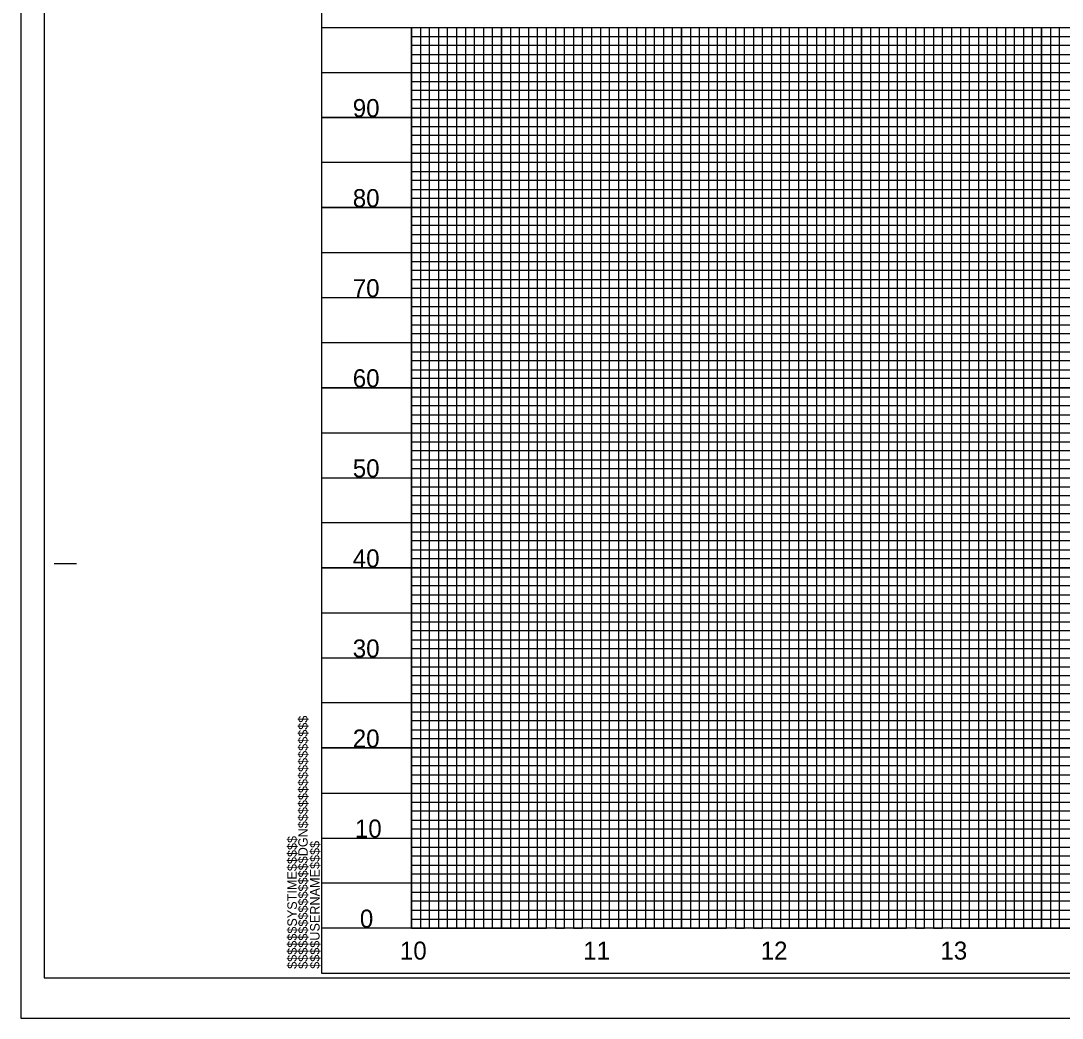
# Model space of a CAD drawing. Extents: x 2186391 to 2188300, y 74582 to 75682.
# Drawn here: x 2186391 to 2186969, y 74582 to 75136 of the extents above; entities that cross this region are included whole.
import ezdxf

# ---------------------------------------------------------------- set-up
doc = ezdxf.new("R2010")
doc.units = 0
for name, color, linetype in [('Old_Level_1', 7, 'Continuous'), ('Old_Level_11', 7, 'Continuous'), ('Old_Level_2', 7, 'Continuous'), ('Old_Level_3', 7, 'Continuous'), ('Scratch_Level_0', 7, 'Continuous'), ('Sheet Border Standard 30in CELL', 7, 'Continuous'), ('Sheet Cutting Line CELL', 7, 'Continuous'), ('Sheet Plot Border Outside CELL', 7, 'Continuous'), ('Sheet Sticker Exception Certification CELL', 7, 'Continuous'), ('Sheet Sticker Incomplete CELL', 7, 'Continuous'), ('Sheet Sticker Preliminary CELL', 7, 'Continuous')]:
    doc.layers.add(name, color=color, linetype=linetype)

msp = doc.modelspace()

# ---------------------------------------------------------------- linework, layer by layer
at = {"layer": 'Old_Level_11'}
for p, q in [((2186557.69, 75132.28), (2188057.58, 75132.28)), ((2186607.69, 75132.28), (2186607.69, 74632.28)), ((2186657.69, 75132.28), (2186657.69, 74632.28)), ((2186707.69, 75132.28), (2186707.69, 74632.28)), ((2186757.69, 75132.28), (2186757.69, 74632.28)), ((2186807.69, 75132.28), (2186807.69, 74632.28)), ((2186857.69, 75132.28), (2186857.69, 74632.28)), ((2186907.69, 75132.28), (2186907.69, 74632.28)), ((2186957.69, 75132.28), (2186957.69, 74632.28)), ((2186557.69, 75082.28), (2188057.58, 75082.28)), ((2186557.69, 75032.28), (2188057.58, 75032.28)), ((2186557.69, 74982.28), (2188057.58, 74982.28)), ((2186557.69, 74932.28), (2188057.58, 74932.28)), ((2186557.69, 74882.28), (2188057.58, 74882.28)), ((2186557.69, 74832.28), (2188057.58, 74832.28)), ((2186557.69, 74782.28), (2188057.58, 74782.28)), ((2186557.69, 74732.28), (2188057.58, 74732.28)), ((2186557.69, 74682.28), (2188057.58, 74682.28))]:
    msp.add_line(p, q, dxfattribs=at)
at = {"layer": 'Old_Level_2'}
for points in [[(2186582.69, 75132.28), (2186632.69, 75132.28), (2186632.69, 74632.28), (2186682.69, 74632.28), (2186682.69, 75132.28), (2186732.69, 75132.28), (2186732.69, 74632.28), (2186782.69, 74632.28), (2186782.69, 75132.28), (2186832.69, 75132.28), (2186832.69, 74632.28), (2186882.69, 74632.28), (2186882.69, 75132.28), (2186932.69, 75132.28), (2186932.69, 74632.28), (2186982.69, 74632.28)], [(2186557.69, 75107.28), (2188057.69, 75107.28)], [(2188057.69, 75057.28), (2186557.69, 75057.28), (2186557.69, 75007.28), (2188057.69, 75007.28)], [(2188057.69, 74957.28), (2186557.69, 74957.28), (2186557.69, 74907.28), (2188057.69, 74907.28)], [(2188057.69, 74857.28), (2186557.69, 74857.28), (2186557.69, 74807.28), (2188057.69, 74807.28)], [(2188057.69, 74757.28), (2186557.69, 74757.28), (2186557.69, 74707.28), (2188057.69, 74707.28)], [(2188057.69, 74657.28), (2186557.69, 74657.28)]]:
    msp.add_lwpolyline(points, dxfattribs=at)
at = {"layer": 'Scratch_Level_0'}
for p, q in [((2186390.69, 75682.28), (2186390.69, 74582.28)), ((2186390.69, 74582.28), (2188074.69, 74582.28))]:
    msp.add_line(p, q, dxfattribs=at)
at = {"layer": 'Sheet Border Standard 30in CELL'}
msp.add_lwpolyline([(2186607.69, 75132.28), (2188007.69, 75132.28), (2188007.69, 74632.28), (2186607.69, 74632.28)], close=True, dxfattribs=at)
msp.add_lwpolyline([(2186607.69, 75132.28), (2188007.69, 75132.28), (2188007.69, 74632.28), (2186607.69, 74632.28)], close=True, dxfattribs=at)
at = {"layer": 'Sheet Cutting Line CELL'}
for p, q in [((2186557.69, 75132.28), (2188057.69, 75132.28)), ((2186409.19, 74834.78), (2186421.69, 74834.78)), ((2188057.69, 74632.28), (2186557.69, 74632.28)), ((2186557.69, 74607.28), (2188057.69, 74607.28)), ((2186557.69, 74607.28), (2186557.69, 74607.28)), ((2186557.69, 74607.28), (2186557.69, 74607.28)), ((2186557.69, 74607.28), (2186557.69, 74607.28)), ((2186557.69, 74607.28), (2186557.69, 74607.28)), ((2186557.69, 74607.28), (2186557.69, 74607.28)), ((2186557.69, 74607.28), (2186557.69, 74607.28)), ((2186557.69, 74607.28), (2186557.69, 74607.28))]:
    msp.add_line(p, q, dxfattribs=at)
msp.add_lwpolyline([(2188057.69, 75657.28), (2186557.69, 75657.28), (2186557.69, 74607.28), (2188057.69, 74607.28)], close=True, dxfattribs=at)
at = {"layer": 'Sheet Plot Border Outside CELL'}
for p, q in [((2186607.69, 75127.28), (2188007.69, 75127.28)), ((2188007.69, 75122.28), (2186607.69, 75122.28)), ((2186607.69, 75117.28), (2188007.69, 75117.28)), ((2188007.69, 75112.28), (2186607.69, 75112.28)), ((2186607.69, 75102.28), (2188007.69, 75102.28)), ((2188007.69, 75097.28), (2186607.69, 75097.28)), ((2186607.69, 75092.28), (2188007.69, 75092.28)), ((2188007.69, 75087.28), (2186607.69, 75087.28)), ((2186607.69, 75077.28), (2188007.69, 75077.28)), ((2188007.69, 75072.28), (2186607.69, 75072.28)), ((2186607.69, 75067.28), (2188007.69, 75067.28)), ((2188007.69, 75062.28), (2186607.69, 75062.28)), ((2186607.69, 75052.28), (2188007.69, 75052.28)), ((2188007.69, 75047.28), (2186607.69, 75047.28)), ((2186607.69, 75042.28), (2188007.69, 75042.28)), ((2188007.69, 75037.28), (2186607.69, 75037.28)), ((2186607.69, 75027.28), (2188007.69, 75027.28)), ((2188007.69, 75022.28), (2186607.69, 75022.28)), ((2186607.69, 75017.28), (2188007.69, 75017.28)), ((2188007.69, 75012.28), (2186607.69, 75012.28)), ((2186607.69, 75002.28), (2188007.69, 75002.28)), ((2188007.69, 74997.28), (2186607.69, 74997.28)), ((2186607.69, 74992.28), (2188007.69, 74992.28)), ((2188007.69, 74987.28), (2186607.69, 74987.28)), ((2186607.69, 74977.28), (2188007.69, 74977.28)), ((2188007.69, 74972.28), (2186607.69, 74972.28)), ((2186607.69, 74967.28), (2188007.69, 74967.28)), ((2188007.69, 74962.28), (2186607.69, 74962.28)), ((2186607.69, 74952.28), (2188007.69, 74952.28)), ((2188007.69, 74947.28), (2186607.69, 74947.28)), ((2186607.69, 74942.28), (2188007.69, 74942.28)), ((2188007.69, 74937.28), (2186607.69, 74937.43)), ((2186607.69, 74927.28), (2188007.69, 74927.28)), ((2188007.69, 74922.28), (2186607.69, 74922.28)), ((2186607.69, 74917.28), (2188007.69, 74917.28)), ((2188007.69, 74912.28), (2186607.69, 74912.28)), ((2186607.69, 74902.28), (2188007.69, 74902.28)), ((2188007.69, 74897.28), (2186607.69, 74897.28)), ((2186607.69, 74892.28), (2188007.69, 74892.28)), ((2188007.69, 74887.28), (2186607.69, 74887.28)), ((2186607.69, 74877.28), (2188007.69, 74877.28)), ((2188007.69, 74872.28), (2186607.69, 74872.28)), ((2186607.69, 74867.28), (2188007.69, 74867.28)), ((2188007.69, 74862.28), (2186607.69, 74862.28)), ((2186607.69, 74852.28), (2188007.69, 74852.28)), ((2188007.69, 74847.28), (2186607.69, 74847.28)), ((2186607.69, 74842.28), (2188007.69, 74842.28)), ((2188007.69, 74837.28), (2186607.69, 74837.28)), ((2186607.69, 74827.28), (2188007.69, 74827.28)), ((2188007.69, 74822.28), (2186607.69, 74822.28)), ((2186607.69, 74817.28), (2188007.69, 74817.28)), ((2188007.69, 74812.28), (2186607.69, 74812.28)), ((2186607.69, 74802.28), (2188007.69, 74802.28)), ((2188007.69, 74797.28), (2186607.69, 74797.28)), ((2186607.69, 74792.28), (2188007.69, 74792.28)), ((2188007.69, 74787.28), (2186607.69, 74787.28)), ((2186607.69, 74777.28), (2188007.69, 74777.28)), ((2188007.69, 74772.28), (2186607.69, 74772.28)), ((2186607.69, 74767.28), (2188007.69, 74767.28)), ((2188007.69, 74762.28), (2186607.69, 74762.28)), ((2186607.69, 74752.28), (2188007.69, 74752.28)), ((2188007.69, 74747.28), (2186607.69, 74747.28)), ((2186607.69, 74742.28), (2188007.69, 74742.28)), ((2188007.69, 74737.28), (2186607.69, 74737.28)), ((2186607.69, 74727.28), (2188007.69, 74727.28)), ((2188007.69, 74722.28), (2186607.69, 74722.28)), ((2186607.69, 74717.28), (2188007.69, 74717.28)), ((2188007.69, 74712.28), (2186607.69, 74712.28)), ((2186607.69, 74702.28), (2188007.69, 74702.28)), ((2188007.69, 74697.28), (2186607.69, 74697.28)), ((2186607.69, 74692.28), (2188007.69, 74692.28)), ((2188007.69, 74687.28), (2186607.69, 74687.28)), ((2186607.69, 74677.28), (2188007.69, 74677.28)), ((2188007.69, 74672.28), (2186607.69, 74672.28)), ((2186607.69, 74667.28), (2188007.69, 74667.28)), ((2188007.69, 74662.28), (2186607.69, 74662.28)), ((2186607.69, 74652.28), (2188007.69, 74652.28)), ((2188007.69, 74647.28), (2186607.69, 74647.28)), ((2186607.69, 74642.28), (2188007.69, 74642.28)), ((2186607.69, 74637.28), (2188007.69, 74637.28))]:
    msp.add_line(p, q, dxfattribs=at)
for points in [[(2186607.69, 75132.28), (2186612.69, 75132.28), (2186612.69, 74632.28), (2186617.69, 74632.28), (2186617.69, 75132.28), (2186622.69, 75132.28), (2186622.69, 74632.28), (2186627.69, 74632.28), (2186627.69, 75132.28), (2186637.69, 75132.28), (2186637.69, 74632.28), (2186642.69, 74632.28), (2186642.69, 75132.28), (2186647.69, 75132.28), (2186647.69, 74632.28), (2186652.69, 74632.28), (2186662.69, 74632.28), (2186667.69, 74632.28), (2186667.69, 75132.28), (2186672.69, 75132.28), (2186672.69, 74632.28), (2186677.69, 74632.28), (2186677.69, 75132.28), (2186687.69, 75132.28), (2186687.69, 74632.28), (2186692.69, 74632.28), (2186692.69, 75132.28), (2186697.69, 75132.28), (2186697.69, 74632.28), (2186702.69, 74632.28), (2186702.69, 75132.28), (2186712.69, 75132.28), (2186712.69, 74632.28), (2186717.69, 74632.28), (2186717.69, 75132.28), (2186722.69, 75132.28), (2186722.69, 74632.28), (2186727.69, 74632.28), (2186727.69, 75132.28), (2186737.69, 75132.28), (2186737.69, 74632.28), (2186742.69, 74632.28), (2186742.69, 75132.28), (2186747.69, 75132.28), (2186747.69, 74632.28), (2186752.69, 74632.28), (2186752.69, 75132.28), (2186762.69, 75132.28), (2186762.69, 74632.28), (2186767.69, 74632.28), (2186767.69, 75132.28), (2186772.69, 75132.28), (2186772.69, 74632.28), (2186777.69, 74632.28), (2186777.69, 75132.28), (2186787.69, 75132.28), (2186787.69, 74632.28), (2186792.69, 74632.28), (2186792.69, 75132.28), (2186797.69, 75132.28), (2186797.69, 74632.28), (2186802.69, 74632.28), (2186802.69, 75132.28), (2186812.69, 75132.28), (2186812.69, 74632.28), (2186817.69, 74632.28), (2186817.69, 75132.28), (2186822.69, 75132.28), (2186822.69, 74632.28)], [(2186652.69, 74632.28), (2186652.69, 75132.28), (2186662.69, 75132.28), (2186662.69, 74632.28)], [(2186822.69, 74632.28), (2186827.69, 74632.28), (2186827.69, 75132.28), (2186837.69, 75132.28), (2186837.69, 74632.28), (2186842.69, 74632.28), (2186842.69, 75132.28), (2186847.69, 75132.28), (2186847.69, 74632.28), (2186852.69, 74632.28), (2186852.69, 75132.28), (2186862.69, 75132.28), (2186862.69, 74632.28), (2186867.69, 74632.28), (2186867.69, 75132.28), (2186872.69, 75132.28), (2186872.69, 74632.28), (2186877.69, 74632.28), (2186877.69, 75132.28), (2186887.69, 75132.28), (2186887.69, 74632.28), (2186892.69, 74632.28), (2186892.69, 75132.28), (2186897.69, 75132.28), (2186897.69, 74632.28), (2186902.69, 74632.28), (2186902.69, 75132.28), (2186912.69, 75132.28), (2186912.69, 74632.28), (2186917.69, 74632.28), (2186917.69, 75132.28), (2186922.69, 75132.28), (2186922.69, 74632.28), (2186927.69, 74632.28), (2186927.69, 75132.28), (2186937.69, 75132.28), (2186937.69, 74632.28), (2186942.69, 74632.28), (2186942.69, 75132.28), (2186947.69, 75132.28), (2186947.69, 74632.28), (2186952.69, 74632.28), (2186952.69, 75132.28), (2186962.69, 75132.28), (2186962.69, 74632.28), (2186967.69, 74632.28), (2186967.69, 75132.28), (2186972.69, 75132.28)]]:
    msp.add_lwpolyline(points, dxfattribs=at)
at = {"layer": 'Sheet Sticker Exception Certification CELL'}
msp.add_line((2186557.69, 74632.28), (2186557.69, 74632.28), dxfattribs=at)
for points in [[(2186607.69, 75132.28), (2186607.69, 74632.28), (2186657.69, 74632.28), (2186657.69, 75132.28), (2186707.69, 75132.28), (2186707.69, 74632.28), (2186757.69, 74632.28), (2186757.69, 75132.28), (2186807.69, 75132.28), (2186807.69, 74632.28), (2186857.69, 74632.28), (2186857.69, 75132.28), (2186907.69, 75132.28), (2186907.69, 74632.28), (2186957.69, 74632.28), (2186957.69, 75132.28), (2187007.69, 75132.28)], [(2188057.69, 75082.28), (2186557.69, 75082.28)], [(2188057.69, 75032.28), (2186557.69, 75032.28), (2186557.69, 74982.28), (2188057.69, 74982.28)], [(2188057.69, 74932.28), (2186557.69, 74932.28), (2186557.69, 74882.28), (2188057.69, 74882.28)], [(2188057.69, 74832.28), (2186557.69, 74832.28), (2186557.69, 74782.28), (2188057.69, 74782.28)], [(2188057.69, 74732.28), (2186557.69, 74732.28), (2186557.69, 74732.28), (2186557.69, 74682.28), (2188057.69, 74682.28)], [(2188057.69, 74632.28), (2186557.69, 74632.28)]]:
    msp.add_lwpolyline(points, dxfattribs=at)
at = {"layer": 'Sheet Sticker Incomplete CELL'}
msp.add_lwpolyline([(2186390.69, 74582.28), (2188074.69, 74582.28), (2188074.69, 75682.28), (2186390.69, 75682.28)], close=True, dxfattribs=at)
at = {"layer": 'Sheet Sticker Preliminary CELL'}
msp.add_lwpolyline([(2186403.69, 74604.73), (2188070.19, 74604.73), (2188070.19, 75659.83), (2186403.69, 75659.83)], close=True, dxfattribs=at)

# ---------------------------------------------------------------- texts
at = {"layer": 'Old_Level_1'}
for s, p in [('10', (2186601.27, 74614.78)), ('11', (2186703.11, 74614.78)), ('12', (2186801.66, 74614.78)), ('13', (2186901.5, 74614.78))]:
    msp.add_text(s, height=10, dxfattribs=at).set_placement(p)
at = {"layer": 'Old_Level_3'}
for s, p in [('90', (2186575.08, 75082.53)), ('80', (2186575.08, 75032.53)), ('70', (2186575.08, 74982.53)), ('60', (2186575.08, 74932.53)), ('50', (2186575.08, 74882.53)), ('40', (2186575.08, 74832.53)), ('30', (2186575.08, 74782.53)), ('20', (2186575.08, 74732.53)), ('10', (2186576.27, 74682.53)), ('0', (2186579.03, 74632.53))]:
    msp.add_text(s, height=10, dxfattribs=at).set_placement(p)
at = {"layer": 'Sheet Cutting Line CELL'}
for s, p in [('$$$$$$$$$$$$$$$$DGN$$$$$$$$$$$$$$$$', (2186550.05, 74609.66)), ('$$$$$$SYSTIME$$$$$', (2186544, 74609.66)), ('$$$$USERNAME$$$$', (2186556.63, 74609.67))]:
    msp.add_text(s, height=5.25, rotation=90, dxfattribs=at).set_placement(p)

doc.saveas('drawing.dxf')
